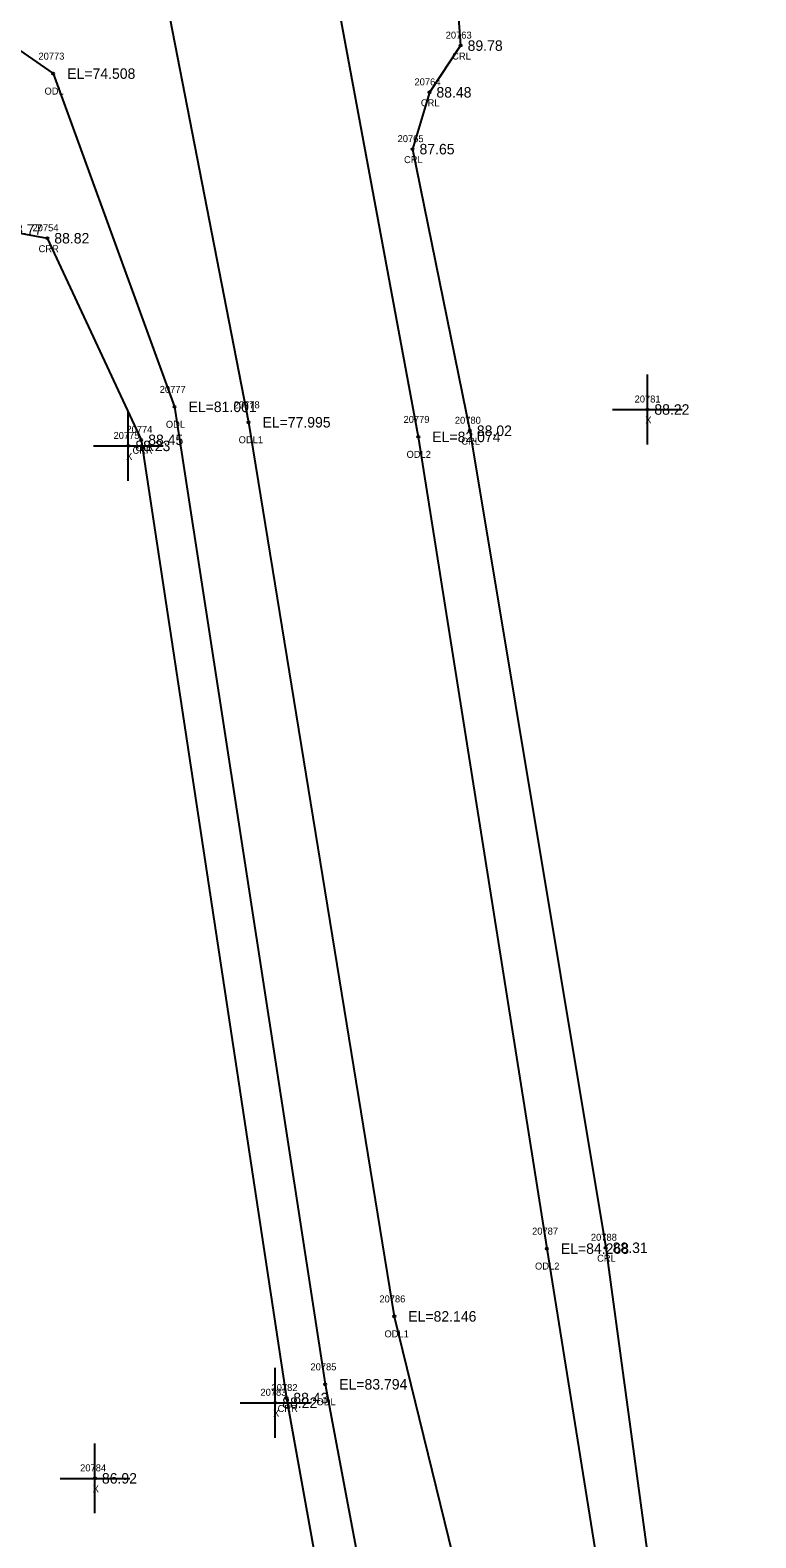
# Model space of a CAD drawing. Extents: x 2530197 to 2532051, y 935230 to 936631.
# Drawn here: x 2531118.7 to 2531222.7, y 935734.5 to 935950.2 of the extents above; entities that cross this region are included whole.
import ezdxf

# ---------------------------------------------------------------- set-up
doc = ezdxf.new("R2010")
doc.units = 0
for name, color, linetype in [('RD_EX_H2O', 7, 'Continuous'), ('RD_EX_H2O_txCode', 7, 'Continuous'), ('RD_EX_Misc', 7, 'Continuous'), ('RD_EX_Misc_txCode', 7, 'Continuous'), ('RD_EX_TX_H2O_ELEV', 7, 'Continuous'), ('RD_EX_TX_Misc_ELEV', 7, 'Continuous'), ('RD_SMD_Locator', 7, 'Continuous')]:
    doc.layers.add(name, color=color, linetype=linetype)

msp = doc.modelspace()

# ---------------------------------------------------------------- linework, layer by layer
at = {"layer": 'RD_EX_H2O'}
for points in [[(2531169.61, 936003.09), (2531168.21, 936006.21), (2531167.04, 936004.54), (2531167.21, 936003.45), (2531176, 935975.44), (2531176.84, 935974.76), (2531177.07, 935973.85), (2531179, 935967.11), (2531180.39, 935948.02), (2531175.92, 935941.33), (2531173.5, 935933.2), (2531181.71, 935892.9), (2531201.16, 935775.97), (2531215.24, 935672.42), (2531231.54, 935569.22), (2531229.65, 935447.9)], [(2531151.41, 935999.3), (2531160.42, 935966.87), (2531174.33, 935892.02), (2531192.74, 935775.85), (2531209.3, 935672.4), (2531227.01, 935569.99), (2531223.19, 935447.63)], [(2531123.96, 935982.91), (2531138.41, 935953.66), (2531150.01, 935894.11), (2531170.89, 935766.15), (2531194.87, 935668.24), (2531198.82, 935567.24), (2531215.76, 935447.86)], [(2531095.07, 935962.75), (2531122.05, 935944.01), (2531139.42, 935896.32), (2531161, 935756.43), (2531179.99, 935655.36), (2531191.29, 935570.65), (2531207.98, 935448.59)], [(2531078.88, 935952.28), (2531078.96, 935951.18), (2531094.18, 935926.97), (2531103.29, 935929.49), (2531106.67, 935929.67), (2531109.75, 935927.85), (2531109.94, 935928.67), (2531111.53, 935928.19), (2531109.98, 935924.15), (2531114.47, 935921.71), (2531121.2, 935920.45), (2531134.65, 935891.6), (2531155.43, 935754.46), (2531173.73, 935652.91), (2531186.19, 935572.51), (2531201.43, 935446.7)]]:
    msp.add_lwpolyline(points, dxfattribs=at)
at = {"layer": 'RD_EX_Misc'}
for p, q in [((2531207.13, 935890.94), (2531207.13, 935900.94)), ((2531132.8, 935885.73), (2531132.8, 935895.73)), ((2531202.13, 935895.94), (2531212.13, 935895.94)), ((2531127.8, 935890.73), (2531137.8, 935890.73)), ((2531153.84, 935748.79), (2531153.84, 935758.79)), ((2531148.84, 935753.79), (2531158.84, 935753.79)), ((2531128.02, 935737.97), (2531128.02, 935747.97)), ((2531123.02, 935742.97), (2531133.02, 935742.97))]:
    msp.add_line(p, q, dxfattribs=at)
at = {"layer": 'RD_SMD_Locator'}
for centre in [(2531180.39, 935948.02), (2531122.05, 935944.01), (2531175.92, 935941.33), (2531173.5, 935933.2), (2531121.2, 935920.45), (2531139.42, 935896.32), (2531150.01, 935894.11), (2531207.13, 935895.94), (2531174.33, 935892.02), (2531181.71, 935892.9), (2531132.8, 935890.73), (2531134.65, 935891.6), (2531192.74, 935775.85), (2531201.16, 935775.97), (2531170.89, 935766.15), (2531161, 935756.43), (2531153.84, 935753.79), (2531155.43, 935754.46), (2531128.02, 935742.97)]:
    msp.add_circle(centre, 0.15, dxfattribs=at)

# ---------------------------------------------------------------- texts
at = {"layer": 'RD_EX_H2O_txCode'}
for s, p in [('20763', (2531178.25, 935949.02)), ('20773', (2531119.93, 935946.01)), ('CRL', (2531179.17, 935946.02)), ('ODL', (2531120.8, 935941.01)), ('20764', (2531173.78, 935942.33)), ('CRL', (2531174.69, 935939.33)), ('20765', (2531171.36, 935934.2)), ('CRL', (2531172.28, 935931.2)), ('20754', (2531119.08, 935921.45)), ('CRR', (2531119.95, 935918.45)), ('20777', (2531137.3, 935898.32)), ('20778', (2531147.89, 935896.11)), ('ODL', (2531138.18, 935893.32)), ('20779', (2531172.21, 935894.02)), ('20780', (2531179.56, 935893.9)), ('20774', (2531132.53, 935892.6)), ('ODL1', (2531148.6, 935891.11)), ('CRL', (2531180.49, 935890.9)), ('CRR', (2531133.4, 935889.6)), ('ODL2', (2531172.64, 935889.02)), ('20787', (2531190.62, 935777.85)), ('20788', (2531199.04, 935776.97)), ('ODL2', (2531191.04, 935772.85)), ('CRL', (2531199.93, 935773.97)), ('20786', (2531168.75, 935768.15)), ('ODL1', (2531169.48, 935763.15)), ('20785', (2531158.88, 935758.43)), ('20782', (2531153.31, 935755.46)), ('ODL', (2531159.75, 935753.43)), ('CRR', (2531154.18, 935752.46))]:
    msp.add_text(s, height=1, dxfattribs=at).set_placement(p)
at = {"layer": 'RD_EX_Misc_txCode'}
for s, p in [('20781', (2531205.3, 935896.94)), ('X', (2531206.82, 935893.94)), ('20775', (2531130.68, 935891.73)), ('X', (2531132.48, 935888.73)), ('20783', (2531151.72, 935754.79)), ('X', (2531153.53, 935751.79)), ('20784', (2531125.9, 935743.97)), ('X', (2531127.7, 935740.97))]:
    msp.add_text(s, height=1, dxfattribs=at).set_placement(p)
at = {"layer": 'RD_EX_TX_H2O_ELEV'}
for s, p in [('89.78', (2531181.39, 935947.27)), ('EL=74.508', (2531124.05, 935943.26)), ('88.48', (2531176.92, 935940.58)), ('87.65', (2531174.5, 935932.45)), ('88.77', (2531115.47, 935920.96)), ('88.82', (2531122.2, 935919.7)), ('EL=81.001', (2531141.42, 935895.57)), ('EL=77.995', (2531152.01, 935893.36)), ('88.45', (2531135.65, 935890.85)), ('EL=82.074', (2531176.33, 935891.27)), ('88.02', (2531182.71, 935892.15)), ('EL=84.268', (2531194.74, 935775.1)), ('88.31', (2531202.16, 935775.22)), ('EL=82.146', (2531172.89, 935765.4)), ('EL=83.794', (2531163, 935755.68)), ('88.43', (2531156.43, 935753.71))]:
    msp.add_text(s, height=1.5, dxfattribs=at).set_placement(p)
at = {"layer": 'RD_EX_TX_Misc_ELEV'}
for s, p in [('88.22', (2531208.13, 935895.19)), ('88.23', (2531133.8, 935889.98)), ('88.22', (2531154.84, 935753.04)), ('86.92', (2531129.02, 935742.22))]:
    msp.add_text(s, height=1.5, dxfattribs=at).set_placement(p)

doc.saveas('drawing.dxf')
